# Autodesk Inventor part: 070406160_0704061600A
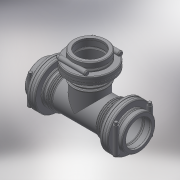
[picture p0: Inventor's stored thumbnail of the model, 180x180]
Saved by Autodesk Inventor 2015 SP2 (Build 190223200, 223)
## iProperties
Created: 2017-05
Part Number: 070406160_0704061600A
Material: Generic
Description: PLASSON TEE 160-160-160
Document SubType Name: Modeling
Designer: KIM
Density: 1 g/cm^3
Appearance: Default
Author: KIM
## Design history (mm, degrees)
derived "070406.ipt"
feature "Solid1::070406.ipt"
tag "TaggingFeature1"
body "Solid1"
other parameters: "d0" = 300.5, "d3" = 208, "d4" = 192, "d5" = 4.8, "d6" = 51, "d7" = 274.4, "d8" = 144, "d9" = 204, "d10" = 51, "d11" = 9.6, "d12" = 51, "d13" = 10.2, "d15" = 4.8, "d17" = 161.6, "d18" = 11.55, "d19" = 0, "d21" = 0, "d23" = 20.16, "d24" = 16, "d25" = 0, "d26" = 1.6, "d29" = 0.1, "d30" = 8, "d31" = 0, "d32" = 4.8, "d34" = 90 deg, "d37" = 0, "d39" = 0, "l_" = 204, "H_" = 601, "d16" = 46.2, "d22" = 28.8
